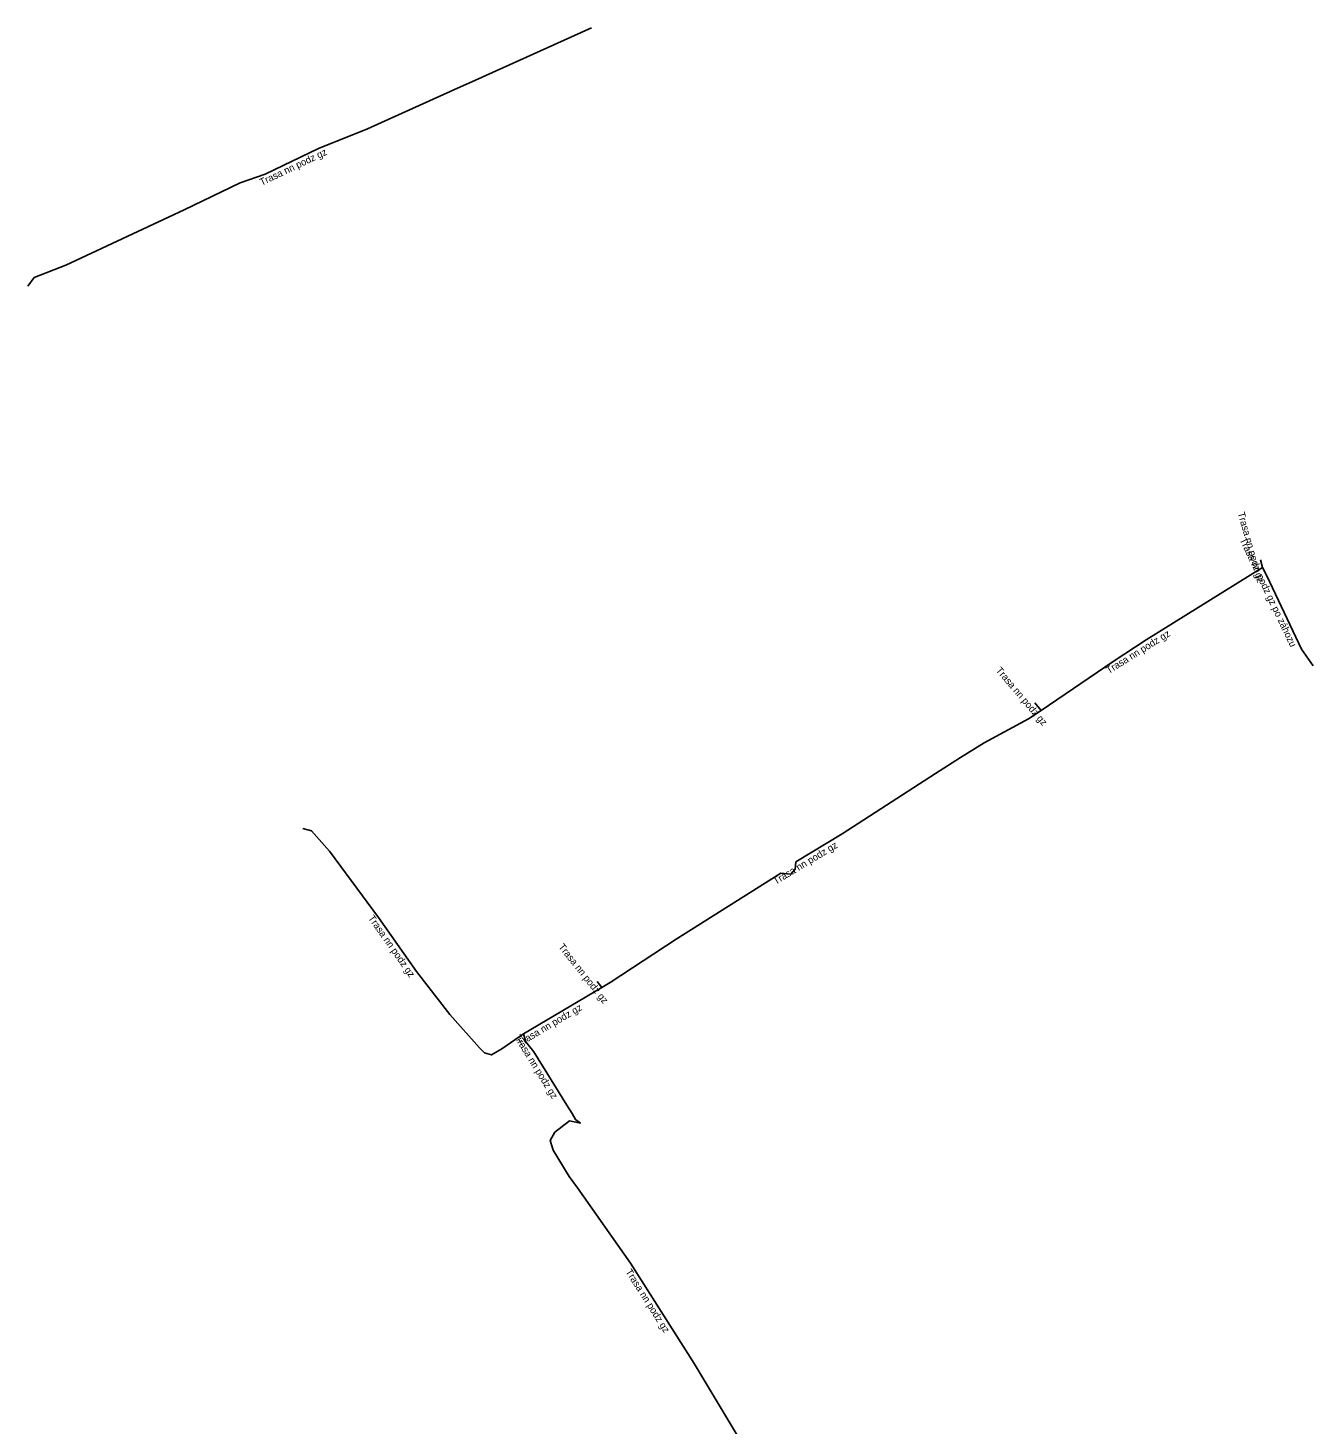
# Model space of a CAD drawing. Extents: x -746106 to -745701, y -1027695 to -1027301.
# Drawn here: x -745934.8 to -745844, y -1027399.2 to -1027300.7 of the extents above; entities that cross this region are included whole.
import ezdxf

# ---------------------------------------------------------------- set-up
doc = ezdxf.new("R2010")
doc.units = 0
doc.layers.add('Popiskový text - Ostatní atributy Trasy', color=7, linetype='Continuous')
doc.layers.add('Spojnice NN', color=7, linetype='Continuous')

msp = doc.modelspace()

# ---------------------------------------------------------------- linework, layer by layer
at = {"layer": 'Spojnice NN'}
for points in [[(-745934.755, -1027318.898), (-745934.312, -1027318.289), (-745932.068, -1027317.427), (-745923.716, -1027313.518), (-745919.765, -1027311.604), (-745918.015, -1027310.993), (-745914.231, -1027309.183), (-745910.784, -1027307.799), (-745904.683, -1027305.048), (-745903.163, -1027304.367), (-745894.959, -1027300.679)], [(-745863.212, -1027348.846), (-745858.138, -1027345.389), (-745855.803, -1027343.866), (-745847.59, -1027338.757)], [(-745847.59, -1027338.757), (-745847.745, -1027338.209)], [(-745847.59, -1027338.757), (-745847.3, -1027339.35), (-745844.85, -1027344.51), (-745844.027, -1027345.689)], [(-745894.24, -1027368.395), (-745893.662, -1027368.044), (-745889, -1027364.992), (-745881.603, -1027360.327), (-745880.893, -1027360.406), (-745880.592, -1027360.042), (-745880.535, -1027359.532), (-745877.268, -1027357.558), (-745870.69, -1027353.302), (-745868.915, -1027352.167), (-745867.238, -1027351.122), (-745864.106, -1027349.431), (-745863.212, -1027348.846)], [(-745863.212, -1027348.846), (-745863.666, -1027348.312)], [(-745915.346, -1027357.171), (-745914.726, -1027357.347), (-745913.459, -1027358.763), (-745909.998, -1027363.454), (-745907.321, -1027367.274), (-745904.964, -1027370.289), (-745902.866, -1027372.656), (-745902.524, -1027373.001), (-745902.031, -1027373.146), (-745901.29, -1027372.719), (-745899.777, -1027371.659)], [(-745899.777, -1027371.659), (-745894.24, -1027368.395)], [(-745894.24, -1027368.395), (-745894.572, -1027367.976)], [(-745899.777, -1027371.659), (-745899.596, -1027372.231), (-745899.049, -1027372.926), (-745896.721, -1027376.705), (-745896.344, -1027377.294), (-745896.106, -1027377.713), (-745895.734, -1027377.966)], [(-745895.734, -1027377.966), (-745896.526, -1027377.796), (-745897.564, -1027378.612), (-745897.883, -1027379.18), (-745897.678, -1027379.881), (-745896.555, -1027381.729), (-745895.957, -1027382.524), (-745892.205, -1027387.837), (-745887.724, -1027394.922), (-745884.676, -1027399.981), (-745883.955, -1027400.552), (-745880.892, -1027405.551), (-745880.454, -1027405.816)]]:
    msp.add_lwpolyline(points, dxfattribs=at)

# ---------------------------------------------------------------- texts
at = {"layer": 'Popiskový text - Ostatní atributy Trasy'}
for s, rotation, p in [('Trasa nn podz gz', 25.56318, (-745918.252, -1027311.827)), ('Trasa nn podz gz', 285.79338, (-745849.352, -1027334.913)), ('Trasa nn podz gz po záhozu', 295.39866, (-745849.231, -1027336.799)), ('Trasa nn podz gz', 31.8842, (-745858.449, -1027346.278)), ('Trasa nn podz gz', 310.37076, (-745866.457, -1027346.033)), ('Trasa nn podz gz', 31.14138, (-745881.961, -1027361.154)), ('Trasa nn podz gz', 305.02221, (-745910.761, -1027363.498)), ('Trasa nn podz gz', 308.39199, (-745897.334, -1027365.537)), ('Trasa nn podz gz', 30.51888, (-745900.032, -1027372.565)), ('Trasa nn podz gz', 301.63456, (-745900.442, -1027371.904)), ('Trasa nn podz gz', 302.31184, (-745892.588, -1027388.448))]:
    msp.add_text(s, height=0.5, rotation=rotation, dxfattribs=at).set_placement(p)

doc.saveas('drawing.dxf')
